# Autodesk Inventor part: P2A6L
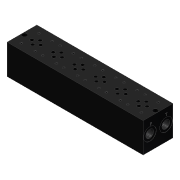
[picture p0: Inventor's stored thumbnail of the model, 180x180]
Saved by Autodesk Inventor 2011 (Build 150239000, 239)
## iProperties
Created: 2010-08
Part Number: P2A6L
Material: По умолчанию
Document SubType Name: Modeling
Designer: tananaev
Density: 1 g/cm^3
Author: tananaev
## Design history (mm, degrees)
derived "P2A2-8L.ipt" dims "d3" = 0, "d4" = 6, "d5" = 5.5, "d7" = 11, "d8" = 11.5, "d11" = 118 deg, "d14" = 308, "d15" = 19.5, "d16" = 14.75, "d17" = 31, "d18" = 32.5, "d21" = 18.75, "d22" = 40.5, "d23" = 7.5, "d24" = 21.5, "d25" = 30.2, "d26" = 12.7, "d27" = 15.5, "d28" = 25.9, "d29" = 5.1, "d31" = 0, "d34" = 5.5, "d36" = 90 deg, "d37" = 11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
node "Твердое тело1"
feature "Твердое тело1::P2A2-8L.ipt" dims "d2" = 70, "d3" = 0, "d4" = 6, "d5" = 5.5, "d7" = 11, "d8" = 11.5, "d10" = 40, "d11" = 118 deg, "d12" = 20, "d14" = 308, "d15" = 19.5, "d16" = 14.75, "d17" = 31, "d18" = 32.5, "d21" = 18.75, "d22" = 40.5, "d23" = 7.5, "d24" = 21.5, "d25" = 30.2, "d26" = 12.7, "d27" = 15.5, "d28" = 25.9, "d29" = 5.1, "d30" = 30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
tag "Элемент создания маркировки1"
